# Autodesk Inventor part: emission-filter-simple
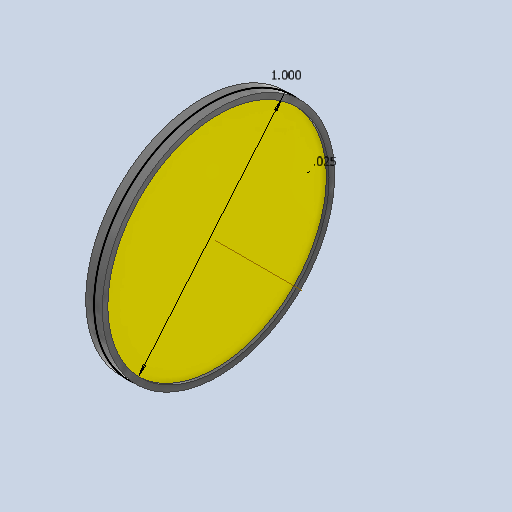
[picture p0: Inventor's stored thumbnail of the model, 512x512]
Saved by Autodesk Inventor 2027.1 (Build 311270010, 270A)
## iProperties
Created: 2026-08
Part Number: emission-filter-simple
Material: Generic
Document SubType Name: Modeling
Designer: dunge
Density: 1 g/cm^3
Appearance: Default
Author: dunge
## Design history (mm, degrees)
sketch "Sketch1"
  geometry: C1 r 12.7 at (0, 0); C2 r 13.335 at (0, 0); 1 further point
  constraints: 2 centre point, 2 coincident
  dimensions: "d0" = 25.4 diameter of C1; "d1" = 0.635 radial gap between concentric circles of C2 C1
extrude "Extrusion1" new body sketch "Sketch1" stored distance "d2" = 1.27; taper "d3" = 0 deg
extrude "Extrusion2" join sketch "Sketch1" stored distance "d4" = 1.905; taper "d5" = 0 deg
workpoint "Work Point1"
  workaxis "Work Axis1"
body "Solid1"
node "Finishes"
node "Finish1" dims "Finish1_Area" = 101.3415
node "Finish2" dims "Finish2_Area" = 31.41586
